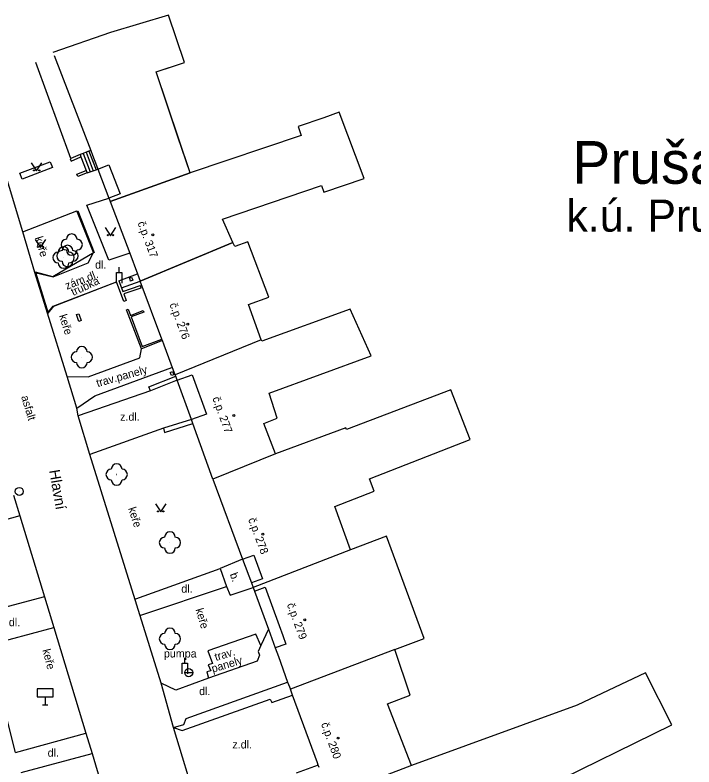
# Model space of a CAD drawing. Extents: x -577457 to -568404, y -1208466 to -1201387.
# Drawn here: x -575396.6 to -575333, y -1204075.1 to -1204004.7 of the extents above; entities that cross this region are included whole.
import ezdxf

# ---------------------------------------------------------------- set-up
doc = ezdxf.new("R2010")
doc.units = 0
for name, color, linetype in [('BUDOVY_MĚŘ', 7, 'Continuous'), ('BUDOVY_NEMĚŘ', 7, 'Continuous'), ('MAP_ZN_BP', 7, 'Continuous'), ('NÁZEV_K_Ú', 7, 'Continuous'), ('NÁZVY_SÍDEL_JEDNOTKY', 7, 'Continuous'), ('NÁZVY_ULIC_TOK_SMĚR', 7, 'Continuous'), ('OBVOD_PILÍŘE', 7, 'Continuous'), ('POMOC_POPIS', 7, 'Continuous'), ('ROZHRANÍ_PLOCH', 7, 'Continuous'), ('ZELEŇ', 7, 'Continuous'), ('ZN_BUDOV', 7, 'Continuous'), ('ZN_DOPLŇKOVÉ', 7, 'Continuous'), ('ZN_KULTUR', 7, 'Continuous'), ('Č_POPIS_ORIENT', 7, 'Continuous')]:
    doc.layers.add(name, color=color, linetype=linetype)

msp = doc.modelspace()

# ---------------------------------------------------------------- linework, layer by layer
at = {"layer": 'BUDOVY_MĚŘ'}
for points in [[(-575392.89, -1204008.49), (-575389.47, -1204017.38)], [(-575389.47, -1204017.38), (-575389.31, -1204017.81)], [(-575388.8, -1204019.14), (-575387.76, -1204018.74), (-575386.72, -1204021.44), (-575387.76, -1204021.84)], [(-575388.93, -1204018.78), (-575388.8, -1204019.14)], [(-575388.8, -1204019.14), (-575387.76, -1204021.84)], [(-575387.76, -1204021.84), (-575387.68, -1204022.06)], [(-575387.68, -1204022.06), (-575387.64, -1204022.16)], [(-575387.64, -1204022.16), (-575385.82, -1204027.01)], [(-575385.09, -1204028.94), (-575384.84, -1204029.61)], [(-575382.81, -1204035.04), (-575384.84, -1204029.61)], [(-575382.75, -1204035.19), (-575382.81, -1204035.04)], [(-575382.59, -1204035.61), (-575382.75, -1204035.19)], [(-575381.56, -1204038.38), (-575381.71, -1204037.97)], [(-575381.51, -1204038.52), (-575381.56, -1204038.38)], [(-575381.37, -1204038.9), (-575379.96, -1204038.39), (-575378.64, -1204042.07), (-575380.05, -1204042.57)], [(-575381.37, -1204038.9), (-575381.51, -1204038.52)], [(-575380.05, -1204042.57), (-575381.37, -1204038.9)], [(-575379.91, -1204042.95), (-575380.05, -1204042.57)], [(-575378.03, -1204048.17), (-575379.91, -1204042.95)], [(-575378.03, -1204048.17), (-575375.25, -1204055.66)], [(-575375.25, -1204055.66), (-575374.21, -1204055.27), (-575373.39, -1204057.49), (-575374.42, -1204057.87)], [(-575375.25, -1204055.66), (-575374.42, -1204057.87)], [(-575374.42, -1204057.87), (-575374.26, -1204058.31)], [(-575374.26, -1204058.31), (-575374.14, -1204058.64)], [(-575374.14, -1204058.64), (-575373.15, -1204058.28), (-575371.84, -1204061.87)], [(-575374.14, -1204058.64), (-575372.83, -1204062.22)], [(-575372.83, -1204062.22), (-575372.19, -1204063.96)], [(-575371.49, -1204062.81), (-575371.2, -1204063.6), (-575372.19, -1204063.96)], [(-575372.19, -1204063.96), (-575371.9, -1204064.76)], [(-575371.04, -1204067.18), (-575370.78, -1204067.81)], [(-575370.74, -1204067.91), (-575370.78, -1204067.81)], [(-575370.58, -1204068.39), (-575370.74, -1204067.91)], [(-575368.25, -1204074.73), (-575370.58, -1204068.39)], [(-575368.17, -1204074.95), (-575368.25, -1204074.73)], [(-575368.09, -1204075.17), (-575368.17, -1204074.95)]]:
    msp.add_lwpolyline(points, dxfattribs=at)
at = {"layer": 'BUDOVY_NEMĚŘ'}
for points in [[(-575380.16, -1204019.48), (-575381.3, -1204016.11), (-575383.34, -1204010.03), (-575381.73, -1204009.49), (-575380.69, -1204009.14), (-575382.19, -1204004.7), (-575387.61, -1204006.32), (-575393, -1204008.2)], [(-575380.16, -1204019.48), (-575383.34, -1204010.03), (-575380.69, -1204009.14), (-575382.19, -1204004.7), (-575387.61, -1204006.32)], [(-575376.16, -1204025.99), (-575377.12, -1204023.81), (-575367.87, -1204020.67), (-575367.66, -1204021.29), (-575363.86, -1204020.01), (-575366.22, -1204013.81), (-575367.66, -1204014.32), (-575370.04, -1204015.15), (-575369.76, -1204015.98), (-575380.16, -1204019.48), (-575387.64, -1204022.16)], [(-575376.16, -1204025.99), (-575377.12, -1204023.81), (-575367.87, -1204020.67), (-575367.66, -1204021.29), (-575363.86, -1204020.01), (-575366.22, -1204013.81), (-575367.66, -1204014.32), (-575370.04, -1204015.15), (-575369.76, -1204015.98), (-575380.16, -1204019.48)], [(-575387.64, -1204022.16), (-575380.16, -1204019.48)], [(-575373.5, -1204035.11), (-575374.7, -1204031.82), (-575372.81, -1204031.13), (-575374.77, -1204025.93), (-575375.99, -1204026.37), (-575376.16, -1204025.99), (-575384.84, -1204029.61)], [(-575384.84, -1204029.61), (-575376.16, -1204025.99)], [(-575372.17, -1204045.79), (-575373.25, -1204042.95), (-575372, -1204042.46), (-575372.76, -1204040.12), (-575363.22, -1204036.62), (-575365.17, -1204032.23), (-575373.44, -1204035.25), (-575373.5, -1204035.11), (-575381.56, -1204038.38)], [(-575365.16, -1204054.78), (-575366.63, -1204050.73), (-575362.93, -1204049.3), (-575363.38, -1204048.13), (-575353.95, -1204044.45), (-575355.75, -1204039.8), (-575365.53, -1204043.5), (-575365.58, -1204043.36), (-575372.17, -1204045.79), (-575378.03, -1204048.17)], [(-575360.99, -1204064.11), (-575358.26, -1204063.09), (-575361.78, -1204053.51), (-575365.16, -1204054.78), (-575374.26, -1204058.31)], [(-575359.43, -1204074.98), (-575361.68, -1204069.21), (-575359.56, -1204068.4), (-575360.99, -1204064.11), (-575370.78, -1204067.81)], [(-575361.05, -1204093.92), (-575352.95, -1204090.85), (-575356.55, -1204081.33), (-575346.68, -1204077.7), (-575347.02, -1204077.02), (-575335.07, -1204071.17), (-575337.53, -1204066.31), (-575343.94, -1204069.31), (-575359.43, -1204074.98), (-575367.09, -1204077.91)]]:
    msp.add_lwpolyline(points, dxfattribs=at)
at = {"layer": 'MAP_ZN_BP'}
for radius in [0.375, 0.0005]:
    msp.add_circle((-575396.16, -1204049.311), radius, dxfattribs=at)
at = {"layer": 'OBVOD_PILÍŘE'}
for points in [[(-575385.79, -1204029.47), (-575385.85, -1204029.32), (-575385.64, -1204029.24), (-575385.53, -1204029.54), (-575385.73, -1204029.62), (-575385.79, -1204029.47)], [(-575390.59, -1204032.67), (-575390.37, -1204033.31), (-575390.59, -1204033.39), (-575390.81, -1204032.75), (-575390.59, -1204032.67)], [(-575381.96, -1204038.31), (-575382.02, -1204038.16), (-575381.81, -1204038.08), (-575381.7, -1204038.38), (-575381.9, -1204038.46), (-575381.96, -1204038.31)]]:
    msp.add_lwpolyline(points, dxfattribs=at)
at = {"layer": 'ROZHRANÍ_PLOCH'}
for points in [[(-575391.32, -1204018.13), (-575394.6, -1204009.15)], [(-575395.83, -1204024.99), (-575399.49, -1204012.87)], [(-575390.19, -1204017.65), (-575390.47, -1204017.76)], [(-575390.47, -1204017.76), (-575390.38, -1204017.99)], [(-575390.38, -1204017.99), (-575389.89, -1204019.25)], [(-575389.91, -1204017.55), (-575390.19, -1204017.65)], [(-575390.19, -1204017.65), (-575389.52, -1204019.38)], [(-575389.63, -1204017.44), (-575389.91, -1204017.55)], [(-575389.91, -1204017.55), (-575389.23, -1204019.29)], [(-575389.47, -1204017.38), (-575389.63, -1204017.44)], [(-575389.63, -1204017.44), (-575388.95, -1204019.2)], [(-575393.06, -1204018.98), (-575395.9, -1204020.06), (-575396.11, -1204019.51), (-575393.26, -1204018.44), (-575393.06, -1204018.98)], [(-575389.89, -1204019.25), (-575389.81, -1204019.47)], [(-575389.81, -1204019.47), (-575389.52, -1204019.38)], [(-575389.52, -1204019.38), (-575389.23, -1204019.29)], [(-575389.23, -1204019.29), (-575388.95, -1204019.2), (-575388.8, -1204019.14)], [(-575385.82, -1204027.01), (-575387.78, -1204027.66), (-575389.83, -1204022.49)], [(-575395.83, -1204024.99), (-575390.76, -1204023.03)], [(-575394.69, -1204028.82), (-575392.99, -1204029.23), (-575389.7, -1204027.91), (-575389.2, -1204026.94), (-575390.76, -1204023.03)], [(-575390.67, -1204023.03), (-575389.16, -1204026.94), (-575393.01, -1204029.2), (-575394.63, -1204028.79)], [(-575394.69, -1204028.82), (-575395.83, -1204024.99)], [(-575393.52, -1204032.62), (-575394.69, -1204028.82)], [(-575394.63, -1204028.79), (-575393.45, -1204032.62)], [(-575386.83, -1204029.59), (-575385.09, -1204028.94)], [(-575393.52, -1204032.62), (-575392.97, -1204031.96), (-575387.06, -1204029.68)], [(-575393.45, -1204032.62), (-575392.93, -1204031.96), (-575387.06, -1204029.68)], [(-575386.58, -1204030.26), (-575384.84, -1204029.61)], [(-575391.66, -1204038.56), (-575393.52, -1204032.62)], [(-575391.66, -1204038.56), (-575389.72, -1204038.59), (-575384.86, -1204036.8), (-575384.73, -1204035.95)], [(-575390.77, -1204041.5), (-575389.08, -1204040.36), (-575381.88, -1204037.71)], [(-575390.77, -1204041.5), (-575391.66, -1204038.56)], [(-575383.87, -1204039.9), (-575390.63, -1204042.22)], [(-575390.63, -1204042.22), (-575390.77, -1204041.5)], [(-575389.55, -1204045.84), (-575390.63, -1204042.22)], [(-575382.67, -1204043.4), (-575389.55, -1204045.84)], [(-575382.88, -1204067.27), (-575389.55, -1204045.84)], [(-575396.71, -1204049.67), (-575396.09, -1204051.59)], [(-575396.09, -1204051.59), (-575402.03, -1204053.24)], [(-575396.09, -1204051.59), (-575393.78, -1204059.18)], [(-575393.78, -1204059.18), (-575400.03, -1204060.84), (-575402.03, -1204053.24)], [(-575375.25, -1204055.66), (-575377.36, -1204056.52)], [(-575385.25, -1204059.38), (-575377.36, -1204056.52)], [(-575377.36, -1204056.52), (-575376.75, -1204058.2)], [(-575384.79, -1204060.91), (-575376.75, -1204058.2)], [(-575376.75, -1204058.2), (-575376.41, -1204059.03), (-575374.26, -1204058.31)], [(-575393.78, -1204059.18), (-575392.91, -1204062.05)], [(-575396.5, -1204073.76), (-575398.46, -1204066.08), (-575398.72, -1204065.51), (-575399.23, -1204063.73), (-575392.91, -1204062.05)], [(-575392.91, -1204062.05), (-575389.92, -1204071.94)], [(-575372.83, -1204062.22), (-575373.55, -1204063.74)], [(-575373.55, -1204063.74), (-575374.02, -1204062.67), (-575378.49, -1204064.23), (-575378.07, -1204065.42), (-575378.47, -1204065.54), (-575378.24, -1204066.1), (-575378.6, -1204066.21), (-575378.44, -1204066.8)], [(-575373.55, -1204063.74), (-575373.8, -1204064.3), (-575373.67, -1204064.64), (-575373.88, -1204065.2), (-575378.44, -1204066.8)], [(-575378.44, -1204066.8), (-575381.49, -1204067.92), (-575382.88, -1204067.27)], [(-575381.73, -1204071.41), (-575382.88, -1204067.27)], [(-575381.73, -1204071.41), (-575380.76, -1204071.13), (-575380.53, -1204070.58), (-575371.04, -1204067.18)], [(-575381.73, -1204071.41), (-575380.92, -1204071.7), (-575372.67, -1204068.76), (-575372.51, -1204069.08), (-575370.58, -1204068.39)], [(-575379.49, -1204078.73), (-575381.73, -1204071.41)], [(-575396.5, -1204073.76), (-575389.92, -1204071.94)], [(-575389.92, -1204071.94), (-575389.34, -1204073.85)], [(-575395.98, -1204075.64), (-575389.34, -1204073.85)], [(-575389.34, -1204073.85), (-575388.85, -1204075.45), (-575387.34, -1204080.54)]]:
    msp.add_lwpolyline(points, dxfattribs=at)
at = {"layer": 'ZELEŇ'}
for centre in [(-575391.25, -1204026.2), (-575392.01, -1204027.41), (-575391.65, -1204027.26), (-575390.3, -1204036.74), (-575387.04, -1204047.72), (-575382.05, -1204054.1), (-575382.05, -1204063.11)]:
    msp.add_circle(centre, 0.0005, dxfattribs=at)
for centre, start, end in [((-575391.75, -1204026.2), 89.99999, 269.99999), ((-575391.25, -1204025.7), 0, 179.99999), ((-575390.75, -1204026.2), 270, 89.99999), ((-575392.01, -1204026.91), 0, 179.99999), ((-575391.65, -1204026.76), 0, 179.99999), ((-575392.51, -1204027.41), 89.99999, 269.99999), ((-575392.15, -1204027.26), 89.99999, 269.99999), ((-575391.25, -1204026.7), 179.99999, 359.99999), ((-575391.51, -1204027.41), 270, 89.99999), ((-575391.15, -1204027.26), 270, 89.99999), ((-575391.65, -1204027.76), 179.99999, 359.99999), ((-575392.01, -1204027.91), 179.99999, 359.99999), ((-575390.8, -1204036.74), 89.99999, 269.99999), ((-575390.3, -1204036.24), 0, 179.99999), ((-575389.8, -1204036.74), 270, 89.99999), ((-575390.3, -1204037.24), 179.99999, 359.99999), ((-575387.04, -1204047.22), 0, 179.99999), ((-575387.54, -1204047.72), 89.99999, 269.99999), ((-575386.54, -1204047.72), 270, 89.99999), ((-575387.04, -1204048.22), 179.99999, 359.99999), ((-575382.05, -1204053.6), 0, 179.99999), ((-575382.55, -1204054.1), 89.99999, 269.99999), ((-575381.55, -1204054.1), 270, 89.99999), ((-575382.05, -1204054.6), 179.99999, 359.99999), ((-575382.05, -1204062.61), 0, 179.99999), ((-575382.55, -1204063.11), 89.99999, 269.99999), ((-575381.55, -1204063.11), 270, 89.99999), ((-575382.05, -1204063.61), 179.99999, 359.99999)]:
    msp.add_arc(centre, 0.5, start, end, dxfattribs=at)
at = {"layer": 'ZN_BUDOV'}
for centre in [(-575383.65, -1204025.29), (-575380.39, -1204033.65), (-575376.08, -1204042.19), (-575373.36, -1204053.31), (-575369.44, -1204061.34), (-575366.32, -1204072.4)]:
    msp.add_circle(centre, 0.0875, dxfattribs=at)
at = {"layer": 'ZN_DOPLŇKOVÉ'}
for p, q in [((-575386.81, -1204028.8), (-575386.81, -1204028.3)), ((-575380.67, -1204065.38), (-575380.67, -1204064.88)), ((-575380.665, -1204066.28), (-575379.915, -1204066.28)), ((-575393.72, -1204068.55), (-575393.72, -1204069.3)), ((-575393.97, -1204069.3), (-575393.47, -1204069.3))]:
    msp.add_line(p, q, dxfattribs=at)
for points in [[(-575391.32, -1204018.13), (-575391.38, -1204018.16), (-575391.29, -1204018.38), (-575390.38, -1204017.99)], [(-575390.47, -1204017.76), (-575391.32, -1204018.13)], [(-575389.31, -1204017.81), (-575388.93, -1204018.78)], [(-575389.81, -1204019.47), (-575390.69, -1204019.81), (-575390.78, -1204019.59), (-575389.89, -1204019.25)], [(-575389.83, -1204022.49), (-575387.76, -1204021.84)], [(-575385.82, -1204027.01), (-575385.09, -1204028.94)], [(-575387.06, -1204029.8), (-575387.06, -1204028.8), (-575386.56, -1204028.8), (-575386.56, -1204029.8)], [(-575386.58, -1204030.26), (-575386.46, -1204030.58), (-575384.85, -1204030.04), (-575384.77, -1204030.27), (-575386.38, -1204030.81), (-575386.14, -1204031.43), (-575386.37, -1204031.51), (-575387.06, -1204029.68)], [(-575386.83, -1204029.59), (-575386.58, -1204030.26)], [(-575382.75, -1204035.19), (-575384.73, -1204035.95), (-575386.11, -1204032.3), (-575385.96, -1204032.24), (-575385.74, -1204032.82), (-575384.56, -1204032.37), (-575384.51, -1204032.52), (-575385.69, -1204032.97), (-575384.64, -1204035.75), (-575382.81, -1204035.04)], [(-575381.71, -1204037.97), (-575382.59, -1204035.61)], [(-575383.87, -1204039.9), (-575384.02, -1204039.53), (-575381.51, -1204038.52)], [(-575381.37, -1204038.9), (-575383.87, -1204039.9)], [(-575380.05, -1204042.57), (-575382.67, -1204043.4)], [(-575382.67, -1204043.4), (-575382.55, -1204043.78), (-575379.91, -1204042.95)], [(-575371.84, -1204061.87), (-575371.49, -1204062.81)], [(-575371.9, -1204064.76), (-575371.04, -1204067.18)], [(-575380.92, -1204066.38), (-575380.92, -1204065.38), (-575380.42, -1204065.38), (-575380.42, -1204066.38)], [(-575368.17, -1204074.95), (-575370.25, -1204075.7)]]:
    msp.add_lwpolyline(points, dxfattribs=at)
msp.add_lwpolyline([(-575394.47, -1204068.55), (-575392.97, -1204068.55), (-575392.97, -1204067.8), (-575394.47, -1204067.8)], close=True, dxfattribs=at)
msp.add_circle((-575380.29, -1204066.28), 0.375, dxfattribs=at)
at = {"layer": 'ZN_KULTUR'}
for points in [[(-575395.03, -1204018.55), (-575394.53, -1204019.3), (-575394.03, -1204018.55)], [(-575388.11, -1204024.61), (-575387.61, -1204025.36), (-575387.11, -1204024.61)], [(-575394.66, -1204025.71), (-575394.16, -1204026.46), (-575393.66, -1204025.71)], [(-575383.42, -1204050.48), (-575382.92, -1204051.23), (-575382.42, -1204050.48)]]:
    msp.add_lwpolyline(points, dxfattribs=at)
for centre in [(-575394.78, -1204019.25), (-575394.28, -1204019.25), (-575387.86, -1204025.31), (-575387.36, -1204025.31), (-575394.41, -1204026.41), (-575393.91, -1204026.41), (-575383.17, -1204051.18), (-575382.67, -1204051.18)]:
    msp.add_circle(centre, 0.05, dxfattribs=at)

# ---------------------------------------------------------------- texts
at = {"layer": 'NÁZEV_K_Ú'}
msp.add_text('k.ú. Prušánky', height=3, dxfattribs=at).set_placement((-575344.94, -1204024.98))
at = {"layer": 'NÁZVY_SÍDEL_JEDNOTKY'}
msp.add_text('Prušánky', height=4, dxfattribs=at).set_placement((-575344.4, -1204020.5))
at = {"layer": 'NÁZVY_ULIC_TOK_SMĚR'}
msp.add_text('Hlavní', height=1, rotation=279.64999, dxfattribs=at).set_placement((-575393.36, -1204047.35))
at = {"layer": 'POMOC_POPIS'}
for s, p in [('dl.', (-575389.06, -1204028.45)), ('z.dl.', (-575386.72, -1204042.69)), ('dl.', (-575380.99, -1204058.79)), ('z.dl.', (-575397.91, -1204061.93)), ('pumpa', (-575382.62, -1204064.86)), ('dl.', (-575379.32, -1204068.38)), ('z.dl.', (-575376.21, -1204073.38)), ('dl.', (-575393.5, -1204074.15))]:
    msp.add_text(s, height=0.75, dxfattribs=at).set_placement(p)
for s, rotation, p in [('zám.dl.', 21.22694, (-575391.7, -1204030.43)), ('trubka', 25.13589, (-575391.1, -1204031.02)), ('trav.panely', 15.73124, (-575388.83, -1204039.54)), ('asfalt', 287.00831, (-575395.99, -1204040.44)), ('b.', 290.41999, (-575376.47, -1204057.07)), ('trav.', 16.70842, (-575377.75, -1204065.19)), ('panely', 16.70842, (-575378.04, -1204066.28))]:
    msp.add_text(s, height=0.75, rotation=rotation, dxfattribs=at).set_placement(p)
at = {"layer": 'ZELEŇ'}
for rotation, p in [(286.57567, (-575394.7, -1204025.55)), (287.38698, (-575392.44, -1204032.85)), (287.61868, (-575385.97, -1204050.9)), (286.71576, (-575379.67, -1204060.37)), (284.31678, (-575393.99, -1204064.16))]:
    msp.add_text('keře', height=0.75, rotation=rotation, dxfattribs=at).set_placement(p)
at = {"layer": 'Č_POPIS_ORIENT'}
for s, rotation, p in [('č.p. 317', 290.54002, (-575385.1, -1204024.17)), ('č.p. 276', 290.52003, (-575382.11, -1204031.8)), ('č.p. 277', 289.85522, (-575378.09, -1204040.58)), ('č.p. 278', 290.41999, (-575374.75, -1204051.92)), ('č.p. 279', 290.15379, (-575371.12, -1204059.9)), ('č.p. 280', 290.07999, (-575367.92, -1204071.08))]:
    msp.add_text(s, height=0.75, rotation=rotation, dxfattribs=at).set_placement(p)

doc.saveas('drawing.dxf')
